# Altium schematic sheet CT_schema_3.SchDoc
size 382 x 218 mm
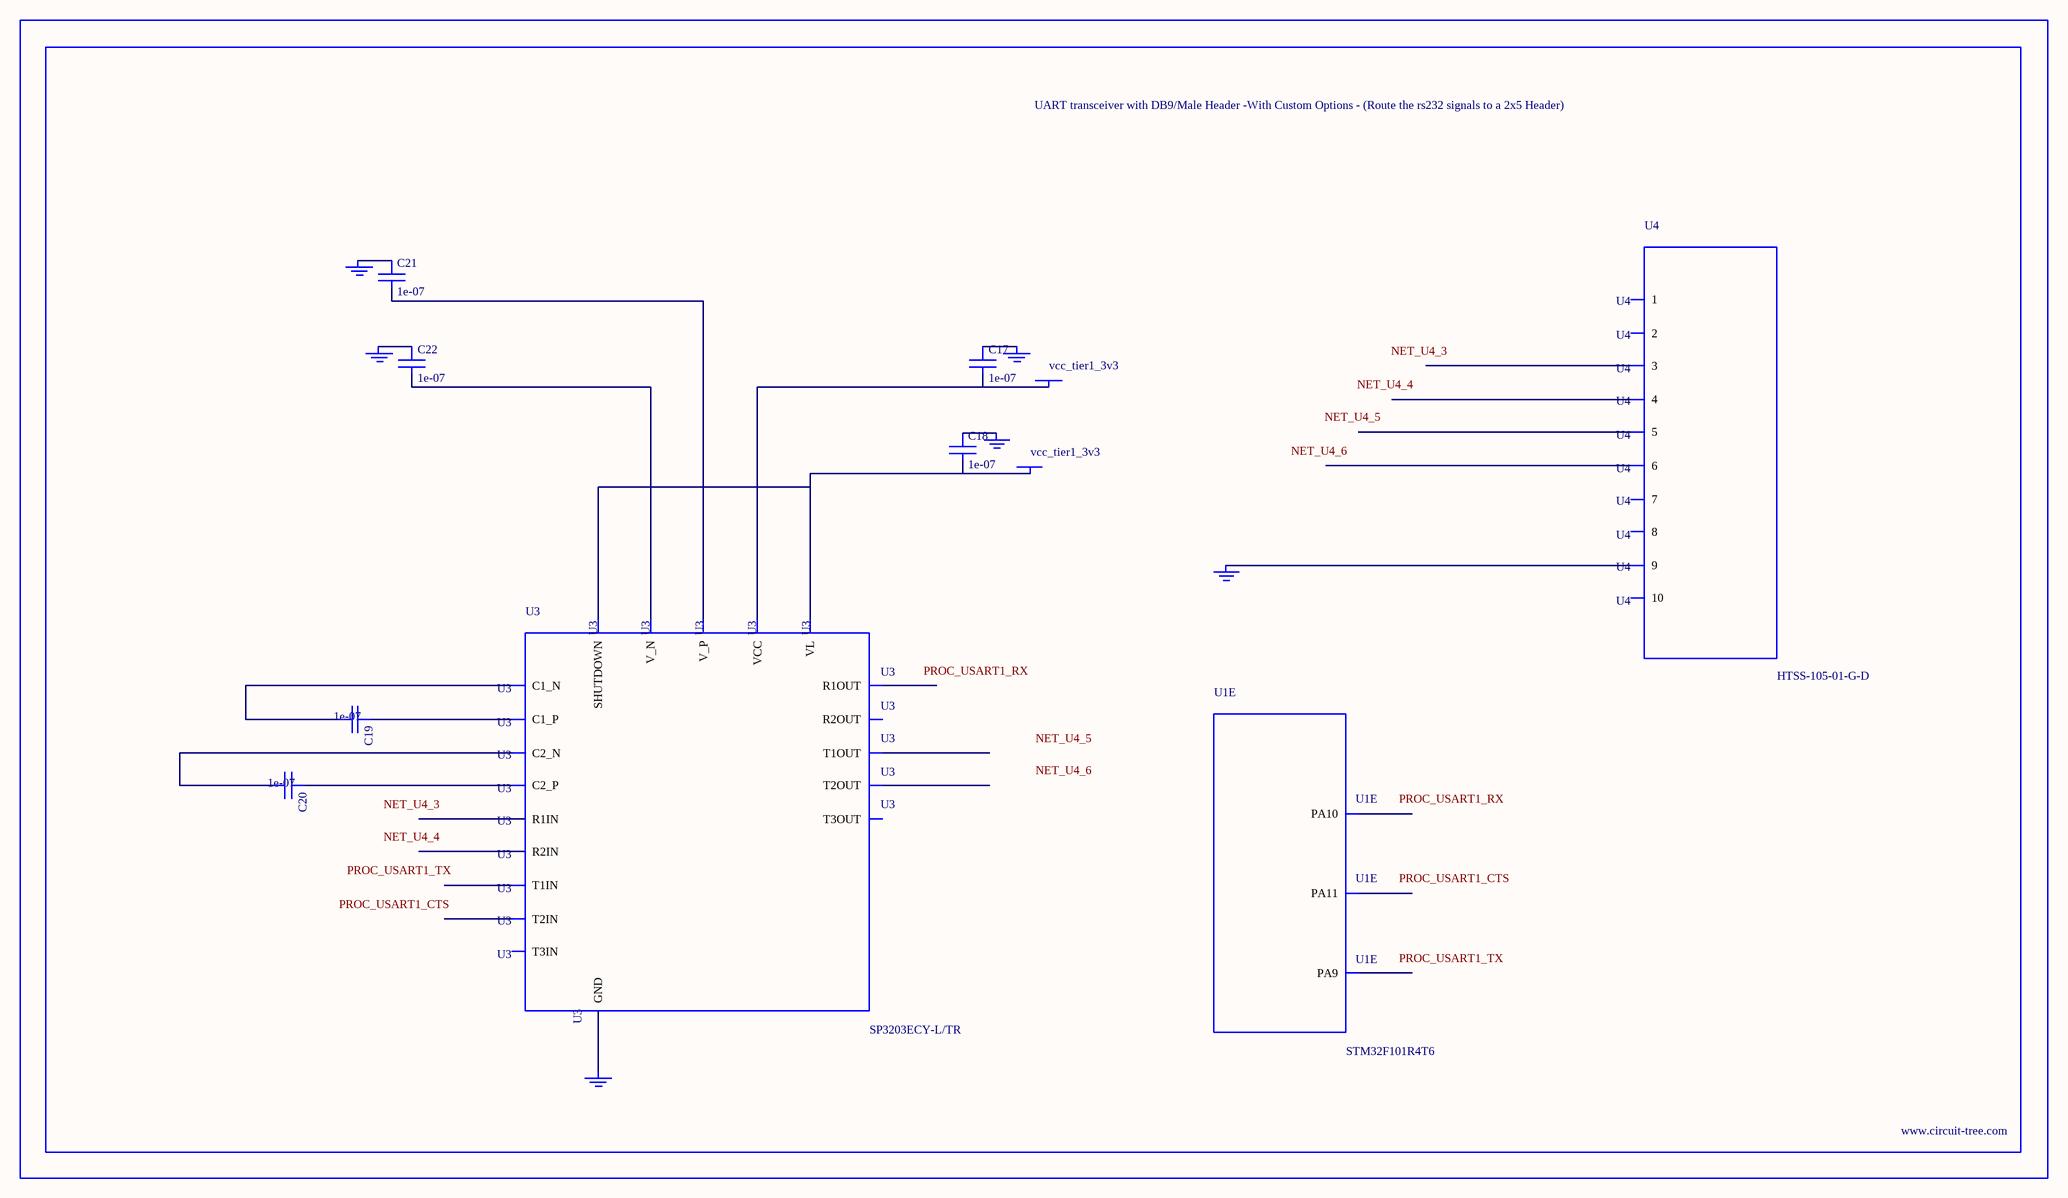
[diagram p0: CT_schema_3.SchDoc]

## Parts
BORDER2  (no value)
C17  1e-07  [C0402]
C18  1e-07  [C0402]
C19  1e-07  [C0402]
C20  1e-07  [C0402]
C21  1e-07  [C0402]
C22  1e-07  [C0402]
GND_INSTANCE_2_0  (no value)
GND_INSTANCE_2_1  (no value)
GND_INSTANCE_2_2  (no value)
GND_INSTANCE_2_3  (no value)
GND_INSTANCE_2_4  (no value)
GND_INSTANCE_2_5  (no value)
POWER_INSTANCE_2_0  vcc_tier1_3v3
POWER_INSTANCE_2_1  vcc_tier1_3v3
U1  STM32F101R4T6  [LQFP64]  (part E of 7)
U3  SP3203ECY-L/TR  [TSSOP20-I]
U4  HTSS-105-01-G-D  [HTSS-105-01-G-D]

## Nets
NetC17_1: C17.1 GND_INSTANCE_2_3.0(GND)
NetC17_2: C17.2 POWER_INSTANCE_2_1.0(PWR) U3.19(VCC)
NetC18_1: C18.1 GND_INSTANCE_2_2.0(GND)
NetC18_2: C18.2 POWER_INSTANCE_2_0.0(PWR) U3.12(VL) U3.20(SHUTDOWN)
NetC19_1: C19.1 U3.1(C1_P)
NetC19_2: C19.2 U3.3(C1_N)
NetC20_1: C20.1 U3.4(C2_P)
NetC20_2: C20.2 U3.5(C2_N)
NetC21_1: C21.1 GND_INSTANCE_2_0.0(GND)
NetC21_2: C21.2 U3.2(V_P)
NetC22_1: C22.1 GND_INSTANCE_2_1.0(GND)
NetC22_2: C22.2 U3.6(V_N)
NetGND_INSTANCE_2_4_0: GND_INSTANCE_2_4.0(GND) U3.18(GND)
NetGND_INSTANCE_2_5_0: GND_INSTANCE_2_5.0(GND) U4.9

Not connected (* = marked no-connect by the designer): U1 42(PA9) 43(PA10) 44(PA11); U3 7(T1IN) 8(T2IN) 9(T3IN) 10(R2OUT) 11(R1OUT) 13(R2IN) 14(R1IN) 15(T3OUT) 16(T2OUT) 17(T1OUT); U4 1 2 3 4 5 6 7 8 10

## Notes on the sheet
- Labels drawn without touching a wire or pin: NET_U4_3, NET_U4_4, NET_U4_5, NET_U4_6, PROC_USART1_CTS, PROC_USART1_RX, PROC_USART1_TX

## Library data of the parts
BORDER2 = BORDER_PAGE2
C17-C22 = C0402C104K3RACTU
GND_INSTANCE_2_0-GND_INSTANCE_2_5 = GND
POWER_INSTANCE_2_0 POWER_INSTANCE_2_1 = PWR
